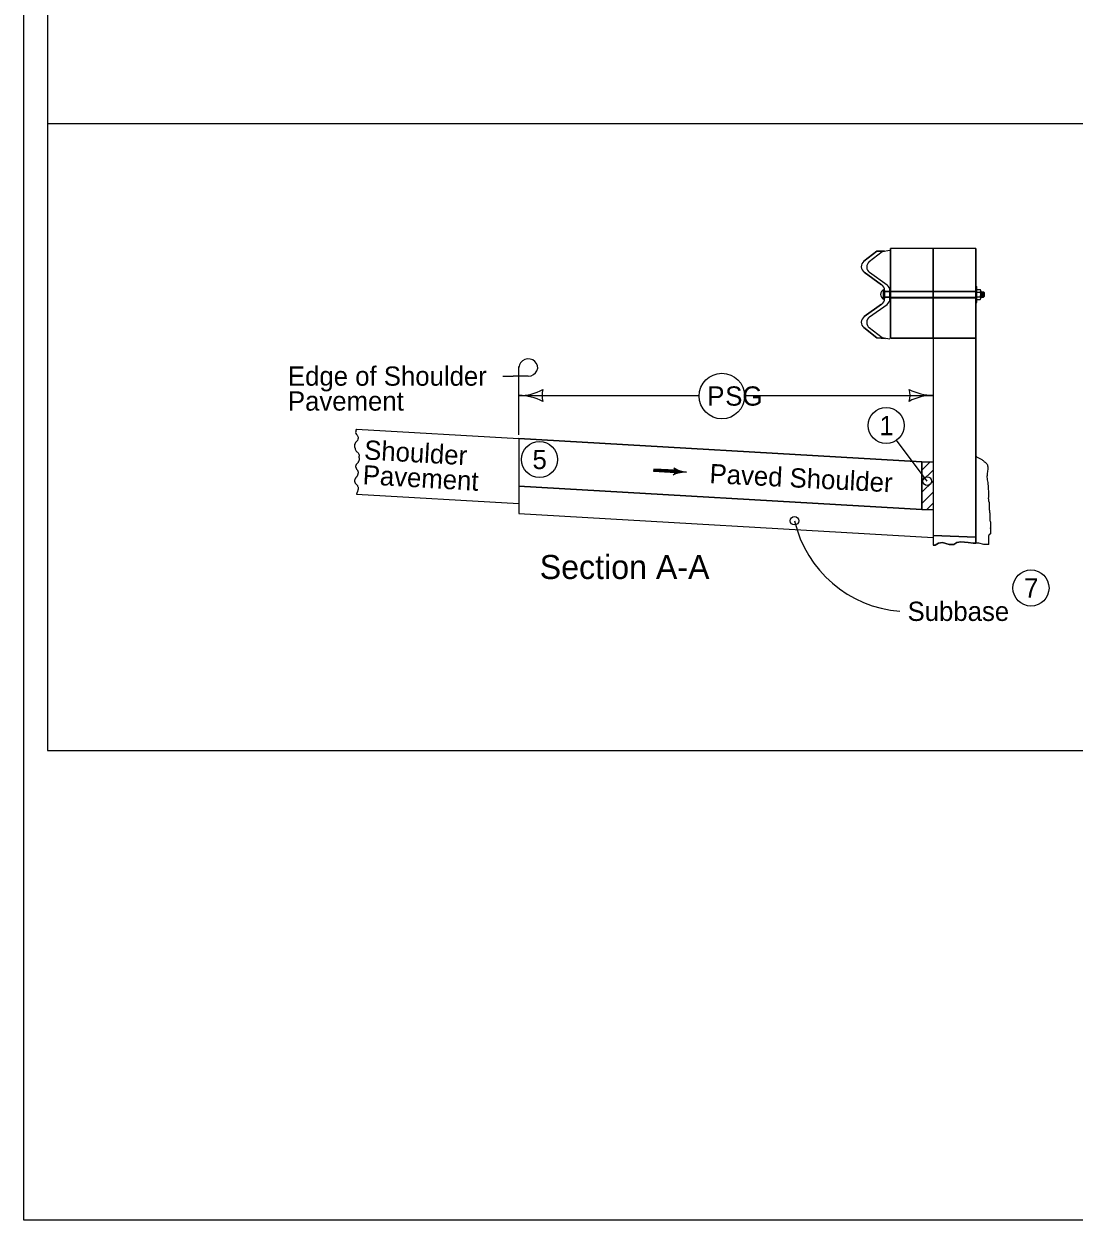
# Model space of a CAD drawing. Extents: x 10133 to 81668, y 5848 to 11018.
# Drawn here: x 10133 to 11006, y 7924 to 8918 of the extents above; entities that cross this region are included whole.
import ezdxf

# ---------------------------------------------------------------- set-up
doc = ezdxf.new("R2010")
doc.units = 0
for name, color, linetype in [('dsnStdLabel', 7, 'Continuous'), ('dsnStdLineWork', 7, 'Continuous'), ('dsnStdNote', 7, 'Continuous'), ('dsnStdShading', 7, 'Continuous'), ('Level 5', 7, 'Continuous'), ('PlanSheetShape', 7, 'Continuous'), ('SheetBorder', 7, 'Continuous'), ('SheetText', 7, 'Continuous'), ('ShtPlotShapeBatchPrint', 7, 'Continuous')]:
    doc.layers.add(name, color=color, linetype=linetype)

msp = doc.modelspace()

# ---------------------------------------------------------------- linework, layer by layer
at = {"layer": 'dsnStdLabel'}
for centre, radius in [((10849.44, 8584.52), 15), ((10561.16, 8556.33), 15), ((10883.56, 8538.4), 3.58), ((10969.88, 8449.47), 15)]:
    msp.add_circle(centre, radius, dxfattribs=at)
at = {"layer": 'dsnStdLineWork'}
for p, q in [((10924.05, 8731.84), (10852.96, 8731.84)), ((10852.96, 8657.19), (10852.96, 8731.84)), ((10888.5, 8657.19), (10888.5, 8731.84)), ((10924.05, 8731.84), (10924.05, 8486.8)), ((10831.02, 8721.08), (10841.78, 8729.48)), ((10835.45, 8720.85), (10846.22, 8729.26)), ((10841.78, 8729.48), (10848.11, 8729.59)), ((10846.22, 8729.26), (10852.56, 8730.38)), ((10845.72, 8701.54), (10831.21, 8711.96)), ((10850.19, 8701.31), (10835.63, 8711.76)), ((10847.34, 8689.44), (10847.34, 8697.52)), ((10847.34, 8695.83), (10852.77, 8695.83)), ((10847.34, 8691.17), (10852.96, 8691.17)), ((10848.12, 8690.1), (10848.11, 8696.91)), ((10848.11, 8690.1), (10848.12, 8693.51)), ((10848.12, 8693.51), (10848.12, 8690.1)), ((10848.29, 8695.83), (10852.96, 8695.83)), ((10852.56, 8693.29), (10852.56, 8696.69)), ((10852.56, 8689.88), (10852.56, 8693.29)), ((10852.56, 8693.29), (10852.56, 8689.88)), ((10852.96, 8696.17), (10924.05, 8696.17)), ((10852.96, 8695.83), (10924.05, 8695.83)), ((10852.96, 8691.17), (10924.05, 8691.17)), ((10924.05, 8700.14), (10924.73, 8700.14)), ((10924.73, 8686.8), (10924.73, 8700.14)), ((10924.73, 8697.51), (10927.7, 8697.51)), ((10924.73, 8695.49), (10927.7, 8695.49)), ((10924.73, 8691.45), (10927.7, 8691.45)), ((10928.06, 8690.44), (10928.06, 8696.5)), ((10928.06, 8695.8), (10930.43, 8695.8)), ((10928.06, 8691.14), (10930.43, 8691.14)), ((10928.95, 8695.8), (10928.95, 8691.14)), ((10929.69, 8695.8), (10929.69, 8691.14)), ((10930.43, 8695.8), (10930.88, 8695.27)), ((10930.43, 8695.8), (10930.43, 8691.14)), ((10930.88, 8691.67), (10930.43, 8691.14)), ((10930.88, 8695.27), (10930.88, 8691.67)), ((10831.21, 8675.05), (10845.72, 8685.47)), ((10835.63, 8674.82), (10850.19, 8685.27)), ((10852.95, 8690.83), (10924.05, 8690.83)), ((10924.05, 8686.8), (10924.73, 8686.8)), ((10924.73, 8689.43), (10927.7, 8689.43)), ((10841.78, 8657.54), (10831.02, 8665.93)), ((10846.22, 8657.32), (10835.45, 8665.73)), ((10848.88, 8656.85), (10841.78, 8657.54)), ((10852.56, 8656.2), (10846.22, 8657.32)), ((10888.5, 8657.19), (10852.96, 8657.19)), ((10888.5, 8657.19), (10888.5, 8484.96)), ((10408.97, 8581.57), (10544.11, 8573.71)), ((10544.11, 8573.71), (10544.11, 8519.7)), ((10544.11, 8573.71), (10879.25, 8554.23)), ((10879.25, 8547.48), (10885.99, 8554.23)), ((10879.25, 8547.48), (10885.99, 8554.23)), ((10879.25, 8547.48), (10885.99, 8554.23)), ((10879.25, 8547.48), (10885.99, 8554.23)), ((10879.25, 8554.23), (10888.49, 8554.23)), ((10879.25, 8554.23), (10879.25, 8514.8)), ((10879.25, 8538.3), (10888.49, 8547.53)), ((10879.25, 8538.3), (10888.49, 8547.53)), ((10879.25, 8538.3), (10888.49, 8547.53)), ((10879.25, 8538.3), (10888.49, 8547.53)), ((10934.1, 8547.46), (10934.1, 8547.46)), ((10879.25, 8514.8), (10544.11, 8534.12)), ((10879.25, 8529.07), (10888.49, 8538.31)), ((10879.25, 8529.07), (10888.49, 8538.31)), ((10879.25, 8529.07), (10888.49, 8538.31)), ((10879.25, 8529.07), (10888.49, 8538.31)), ((10409, 8527.56), (10544.11, 8519.7)), ((10879.25, 8519.84), (10888.49, 8529.08)), ((10544.11, 8519.7), (10544.11, 8511.28)), ((10879.25, 8514.8), (10888.49, 8514.8)), ((10883.35, 8514.8), (10888.49, 8519.94)), ((10544.11, 8511.28), (10888.5, 8491.42))]:
    msp.add_line(p, q, dxfattribs=at)
for points in [[(10928.05, 8690.76), (10928, 8691.03), (10927.96, 8691.2), (10927.87, 8691.36), (10927.75, 8691.45), (10927.83, 8691.55), (10927.91, 8691.77), (10927.97, 8692.08), (10928.05, 8692.83), (10928.05, 8690.76), (10928.03, 8690.9), (10927.99, 8691.12), (10927.91, 8691.33), (10927.79, 8691.44), (10927.83, 8691.53), (10927.89, 8691.68), (10927.99, 8692.18), (10928.03, 8692.56), (10928.03, 8690.95), (10928, 8691.07), (10927.96, 8691.24), (10927.83, 8691.44), (10927.88, 8691.61), (10927.96, 8691.94), (10928.02, 8692.27), (10928.01, 8691.11), (10927.97, 8691.24), (10927.86, 8691.43), (10927.9, 8691.65), (10927.96, 8691.9), (10927.99, 8692.08), (10927.99, 8691.21), (10927.93, 8691.32), (10927.88, 8691.43), (10927.97, 8691.89), (10927.97, 8691.29), (10927.9, 8691.43), (10927.95, 8691.72), (10927.95, 8691.37), (10927.92, 8691.44), (10927.93, 8691.54), (10927.93, 8691.46)], [(10927.76, 8695.49), (10927.83, 8695.54), (10927.91, 8695.64), (10927.99, 8695.86), (10928.05, 8696.15), (10928.05, 8694.2), (10927.99, 8694.71), (10927.94, 8695.08), (10927.82, 8695.41), (10927.76, 8695.49), (10927.82, 8695.5), (10927.92, 8695.65), (10928.01, 8695.87), (10928.03, 8696.03), (10928.03, 8694.49), (10927.96, 8694.98), (10927.9, 8695.25), (10927.8, 8695.47), (10927.83, 8695.48), (10927.97, 8695.7), (10928.01, 8695.85), (10928.01, 8694.75), (10927.82, 8695.46), (10927.99, 8695.74), (10927.99, 8694.88), (10927.85, 8695.45), (10927.97, 8695.67), (10927.98, 8695.03), (10927.87, 8695.43), (10927.96, 8695.6), (10927.96, 8695.19), (10927.89, 8695.42), (10927.94, 8695.53), (10927.94, 8695.33), (10927.91, 8695.4), (10927.92, 8695.45)], [(10934.57, 8523.62), (10934.51, 8523.35), (10934.51, 8523.15), (10934.51, 8522.95), (10934.51, 8522.76), (10934.51, 8522.56), (10934.51, 8522.37), (10934.51, 8522.08), (10934.51, 8521.88), (10934.61, 8521.59), (10934.71, 8521.29), (10934.9, 8521.1), (10934.9, 8520.9), (10935, 8520.71), (10935, 8520.51), (10935, 8520.32), (10935.1, 8520.22), (10935.1, 8520.02), (10935.1, 8519.83), (10935.1, 8519.63), (10935.1, 8519.44), (10935.1, 8519.24), (10935.1, 8518.95), (10935.1, 8518.66), (10935.1, 8518.46), (10935.1, 8518.17), (10935.1, 8517.97), (10935.1, 8517.78), (10935.2, 8517.68), (10935.2, 8517.48), (10935.2, 8517.29), (10935.2, 8517.09), (10935.2, 8516.9), (10935.2, 8516.7), (10935.2, 8516.51), (10935.2, 8516.31), (10935.2, 8516.12), (10935.2, 8515.92), (10935.2, 8515.72), (10935.2, 8515.53), (10935.2, 8515.33), (10935.2, 8515.14), (10935.2, 8514.94), (10935.2, 8514.75), (10935.2, 8514.55), (10935.2, 8514.36), (10935.2, 8514.16), (10935.29, 8514.06), (10935.29, 8513.87), (10935.29, 8513.67), (10935.39, 8513.57), (10935.39, 8513.38), (10935.39, 8513.18), (10935.49, 8513.09), (10935.49, 8512.89), (10935.49, 8512.7), (10935.49, 8512.5), (10935.49, 8512.21), (10935.59, 8511.91), (10935.59, 8511.72), (10935.59, 8511.52), (10935.59, 8511.33), (10935.59, 8511.13), (10935.59, 8510.94), (10935.59, 8510.74), (10935.59, 8510.55), (10935.59, 8510.35), (10935.59, 8510.16), (10935.59, 8509.96), (10935.59, 8509.76), (10935.59, 8509.57), (10935.59, 8509.37), (10935.59, 8509.18), (10935.59, 8508.98), (10935.59, 8508.79), (10935.59, 8508.59), (10935.59, 8508.4), (10935.59, 8508.2), (10935.59, 8508.01), (10935.59, 8507.81), (10935.59, 8507.61), (10935.59, 8507.42), (10935.59, 8507.22), (10935.59, 8507.03), (10935.59, 8506.83), (10935.59, 8506.64), (10935.59, 8506.44), (10935.59, 8506.25), (10935.68, 8506.15), (10935.68, 8505.86), (10935.68, 8505.66), (10935.78, 8505.47), (10935.88, 8505.17), (10935.88, 8504.98), (10935.98, 8504.88), (10935.98, 8504.68), (10936.07, 8504.59), (10936.17, 8504.49), (10936.17, 8504.29), (10936.17, 8504.1), (10936.17, 8503.9), (10936.27, 8503.8), (10936.27, 8503.61), (10936.27, 8503.41), (10936.27, 8503.22), (10936.27, 8503.02), (10936.27, 8502.83), (10936.27, 8502.63), (10936.27, 8502.44), (10936.27, 8502.24), (10936.27, 8502.05), (10936.27, 8501.85), (10936.27, 8501.65), (10936.27, 8501.46), (10936.27, 8501.26), (10936.27, 8501.07), (10936.27, 8500.87), (10936.27, 8500.68), (10936.27, 8500.48), (10936.27, 8500.29), (10936.27, 8500.09), (10936.27, 8499.9), (10936.27, 8499.7), (10936.27, 8499.51), (10936.27, 8499.31), (10936.27, 8499.11), (10936.27, 8498.92), (10936.27, 8498.92), (10936.27, 8499.21), (10936.27, 8499.41), (10936.27, 8499.6), (10936.27, 8499.41), (10936.27, 8499.21), (10936.27, 8499.02), (10936.27, 8498.82), (10936.27, 8498.63), (10936.27, 8498.43), (10936.27, 8498.24), (10936.27, 8498.04), (10936.27, 8497.84), (10936.27, 8497.65), (10936.27, 8497.45), (10936.27, 8497.26), (10936.27, 8497.06), (10936.27, 8496.87), (10936.27, 8496.67), (10936.17, 8496.57), (10936.17, 8496.38), (10936.17, 8496.18), (10936.17, 8495.99), (10936.17, 8495.79), (10936.17, 8495.6), (10936.17, 8495.4), (10936.17, 8495.21), (10936.17, 8495.01), (10936.17, 8494.82), (10936.17, 8494.62), (10936.07, 8494.52), (10935.98, 8494.33), (10935.88, 8494.23), (10935.78, 8494.13), (10935.68, 8494.03), (10935.49, 8493.94), (10935.29, 8493.94), (10935.2, 8493.84), (10935.1, 8493.74), (10935, 8493.64), (10934.8, 8493.55), (10934.71, 8493.45), (10934.71, 8493.25), (10934.61, 8493.15), (10934.61, 8492.96), (10934.61, 8492.76), (10934.61, 8492.57), (10934.61, 8485.75)], [(10934.74, 8485.75), (10930.59, 8485.63), (10926.46, 8486.8), (10921.9, 8486.8), (10917.66, 8487.22), (10911.41, 8487.96), (10908.33, 8487.33), (10905.68, 8485.53), (10901.97, 8485.74), (10896.36, 8487.33), (10893.07, 8486.8), (10890.31, 8485.21), (10888.5, 8484.96)]]:
    msp.add_lwpolyline(points, dxfattribs=at)
for centre, radius, start, end in [((10834.49, 8716.59), 5.68, 127.75002, 234.69086), ((10838.94, 8716.37), 5.68, 127.75002, 234.69086), ((10842.44, 8696.91), 5.68, 360, 54.69099), ((10846.88, 8696.69), 5.68, 360, 54.69099), ((10849.42, 8693.49), 4.54, 117.20289, 242.8461), ((10842.44, 8690.1), 5.68, 305.30901, 0), ((10846.88, 8689.88), 5.68, 305.30901, 0), ((10834.49, 8670.42), 5.68, 125.30914, 232.24998), ((10838.94, 8670.2), 5.68, 125.30914, 232.24998)]:
    msp.add_arc(centre, radius, start, end, dxfattribs=at)
for centre in [(10927.7, 8696.5), (10927.7, 8690.44)]:
    msp.add_ellipse(centre, major_axis=(0, -1.01), ratio=0.362258, start_param=6.283156, end_param=9.424748, dxfattribs=at)
for points in [[(10408.97, 8581.57), (10408.47, 8577.97), (10409.51, 8576.47), (10410.38, 8574.17), (10409.77, 8572.11), (10407.86, 8569.73), (10407.34, 8567.83), (10407.86, 8565.54), (10408.73, 8563.16), (10409.77, 8562.45), (10411.16, 8559.91), (10411.15, 8559.07)], [(10409.18, 8541.96), (10409.39, 8542.21), (10409.59, 8542.47), (10409.94, 8543.03), (10410.23, 8543.62), (10410.34, 8543.93), (10410.44, 8544.24), (10410.57, 8544.86), (10410.62, 8545.48), (10410.58, 8546.07), (10410.52, 8546.35), (10410.48, 8546.48), (10410.43, 8546.61), (10410.23, 8546.99), (10409.94, 8547.35), (10409.64, 8547.72), (10409.39, 8548.12), (10409.25, 8548.4), (10409.12, 8548.68), (10408.86, 8549.26), (10408.65, 8549.82), (10408.58, 8550.12), (10408.53, 8550.41), (10408.52, 8550.54), (10408.52, 8550.67), (10408.67, 8551.44), (10408.88, 8551.96), (10409.13, 8552.47), (10409.58, 8553.11), (10410.1, 8553.65), (10410.61, 8554.2), (10410.84, 8554.51), (10411.04, 8554.85), (10411.25, 8555.32), (10411.4, 8555.8), (10411.51, 8556.27), (10411.54, 8556.51), (10411.55, 8556.63), (10411.56, 8556.75), (10411.51, 8557.26), (10411.36, 8557.77), (10411.31, 8557.9), (10411.26, 8558.03), (10411.21, 8558.15), (10411.18, 8558.29), (10411.15, 8559.07)], [(10934.57, 8523.62), (10934.89, 8526.52), (10934.67, 8531.39), (10934.23, 8537.14), (10933.56, 8541.56), (10933.78, 8544.88), (10934.23, 8549.08), (10933.56, 8552.17), (10931.35, 8554.16), (10929.36, 8555.93), (10927.15, 8557.04), (10924.94, 8558.36), (10924.06, 8559.03)], [(10409.18, 8541.96), (10408.97, 8541.73), (10408.72, 8541.49), (10408.49, 8541.25), (10408.3, 8540.98), (10408.16, 8540.7), (10408.02, 8540.41), (10407.76, 8539.84), (10407.65, 8539.56), (10407.56, 8539.27), (10407.49, 8538.98), (10407.46, 8538.83), (10407.44, 8538.68), (10407.45, 8538.17), (10407.58, 8537.65), (10407.79, 8537.14), (10408.04, 8536.63), (10408.49, 8535.99), (10409.01, 8535.44), (10409.52, 8534.9), (10409.75, 8534.59), (10409.95, 8534.25), (10410.35, 8533.3), (10410.46, 8532.83), (10410.47, 8532.35), (10410.43, 8532.06), (10410.39, 8531.77), (10410.33, 8531.49), (10410.26, 8531.2), (10409.95, 8530.05), (10409.77, 8529.44), (10409.58, 8528.84), (10409.35, 8528.25), (10409.22, 8527.96), (10409.08, 8527.68), (10409, 8527.56)]]:
    msp.add_spline(points, degree=3, dxfattribs=at)
at = {"layer": 'dsnStdNote'}
msp.add_circle((10773.25, 8505.44), 3.54, dxfattribs=at)
msp.add_circle((10773.25, 8505.44), 3.54, dxfattribs=at)
at = {"layer": 'dsnStdShading'}
for p, q in [((12307.76, 8835.36), (10152.18, 8835.36)), ((10883.56, 8538.4), (10858.18, 8572.33))]:
    msp.add_line(p, q, dxfattribs=at)
at = {"layer": 'Level 5'}
msp.add_circle((10561.16, 8556.33), 15, dxfattribs=at)
at = {"layer": 'PlanSheetShape'}
for p, q in [((10831.21, 8711.96), (10845.72, 8701.54)), ((10845.72, 8685.47), (10831.21, 8675.05)), ((10879.25, 8554.23), (10544.11, 8573.71)), ((10544.11, 8573.71), (10544.11, 8534.12)), ((10879.25, 8514.8), (10879.25, 8554.23)), ((10544.11, 8534.12), (10879.25, 8514.8))]:
    msp.add_line(p, q, dxfattribs=at)
for points in [[(10888.5, 8696.17), (10888.5, 8731.84), (10852.96, 8731.84), (10852.96, 8696.17), (10852.96, 8696.17), (10888.5, 8696.17)], [(10924.05, 8696.17), (10924.05, 8700.16), (10924.05, 8731.84), (10888.5, 8731.84), (10888.5, 8696.17), (10924.05, 8696.17)], [(10835.46, 8720.86), (10835.45, 8720.85), (10846.22, 8729.26), (10848.11, 8729.59), (10841.78, 8729.48), (10831.02, 8721.08)], [(10850.16, 8701.33), (10850.19, 8701.31), (10835.63, 8711.76), (10835.66, 8711.74)], [(10848.11, 8696.91), (10848.11, 8695.83), (10852.56, 8695.83), (10852.56, 8696.69), (10852.56, 8696.69)], [(10852.56, 8689.88), (10852.56, 8689.88), (10852.56, 8691.17), (10848.12, 8691.17), (10848.12, 8690.1), (10848.12, 8691.17), (10848.11, 8691.17), (10848.11, 8690.1)], [(10852.96, 8695.83), (10852.96, 8691.17), (10852.96, 8691.17), (10888.5, 8691.17), (10888.5, 8695.83), (10852.96, 8695.83), (10852.96, 8695.83)], [(10924.05, 8691.17), (10924.05, 8695.83), (10888.5, 8695.83), (10888.5, 8691.17), (10924.05, 8691.17)], [(10835.66, 8674.84), (10835.63, 8674.82), (10850.19, 8685.27), (10850.16, 8685.25)], [(10852.96, 8690.83), (10852.96, 8657.19), (10888.5, 8657.19), (10888.5, 8690.83), (10852.96, 8690.83)], [(10924.05, 8657.19), (10924.05, 8686.83), (10924.05, 8690.83), (10888.5, 8690.83), (10888.5, 8657.19), (10924.05, 8657.19)], [(10831.02, 8665.93), (10841.78, 8657.54), (10848.88, 8656.85), (10846.22, 8657.32), (10835.45, 8665.73), (10835.46, 8665.71)], [(10924.05, 8491.85), (10924.05, 8657.19), (10888.5, 8657.19), (10888.5, 8554.22), (10888.5, 8547.53), (10888.5, 8547.53), (10888.5, 8547.53), (10888.5, 8538.3), (10888.5, 8538.3), (10888.5, 8538.3), (10888.5, 8529.16), (10888.5, 8529.16), (10888.5, 8529.16), (10888.5, 8522.23), (10888.5, 8493.01), (10924.05, 8491.85)], [(10924.05, 8491.85), (10888.5, 8493.01), (10888.5, 8484.96), (10890.31, 8485.21), (10893.07, 8486.8), (10896.36, 8487.33), (10901.97, 8485.74), (10905.68, 8485.53), (10908.33, 8487.33), (10911.41, 8487.96), (10917.66, 8487.22), (10921.9, 8486.8), (10924.05, 8486.8), (10924.05, 8491.85)]]:
    msp.add_lwpolyline(points, dxfattribs=at)
msp.add_lwpolyline([(10852.56, 8695.83), (10848.11, 8695.83), (10848.11, 8692.37), (10848.12, 8693.51), (10848.12, 8691.17), (10852.56, 8691.17)], close=True, dxfattribs=at)
for centre, start, end in [((10834.49, 8716.59), 127.75002, 234.69086), ((10838.94, 8716.37), 127.75002, 234.69086), ((10842.44, 8696.91), 0, 54.69099), ((10846.88, 8696.69), 0, 54.69099), ((10842.44, 8690.1), 305.30901, 0), ((10846.88, 8689.88), 305.30901, 0), ((10834.49, 8670.42), 125.30914, 232.24998), ((10838.94, 8670.2), 125.30914, 232.24998)]:
    msp.add_arc(centre, 5.68, start, end, dxfattribs=at)
at = {"layer": 'SheetBorder'}
msp.add_lwpolyline([(10132.52, 9944.02), (13267.53, 9944.02), (13267.53, 7924.02), (10132.52, 7924.02)], close=True, dxfattribs=at)
at = {"layer": 'SheetText'}
for p, q in [((10544.11, 8612.79), (10544.11, 8633.65)), ((10530.74, 8625.64), (10539.43, 8625.64)), ((10551.92, 8625.64), (10539.43, 8625.64)), ((10544.11, 8576.86), (10544.11, 8612.79)), ((10544.11, 8609.47), (10693.94, 8609.47)), ((10731.8, 8609.63), (10888.5, 8609.63)), ((10674.32, 8546.37), (10656.11, 8547.42)), ((10674.21, 8545.43), (10674.21, 8545.43)), ((10674.33, 8547.37), (10674.33, 8547.37))]:
    msp.add_line(p, q, dxfattribs=at)
for points in [[(10674.34, 8547.31), (10656.18, 8548.36), (10656.05, 8546.48), (10674.21, 8545.43), (10674.27, 8547.04), (10656.4, 8548.14), (10656.34, 8546.64), (10673.83, 8545.69), (10673.95, 8546.81), (10656.63, 8547.87), (10656.61, 8546.87), (10673.62, 8545.89), (10673.71, 8546.59), (10656.82, 8547.65), (10656.8, 8547.09), (10673.41, 8546.15)], [(10673.94, 8548.56), (10674.63, 8547.4), (10674.61, 8545.75), (10673.85, 8544.35), (10676.61, 8545.22), (10679.8, 8545.87), (10680.7, 8546), (10678.46, 8546.55), (10675.23, 8547.78), (10674.29, 8548.31), (10674.41, 8544.8), (10679.36, 8546.02), (10674.72, 8547.6), (10674.73, 8545.18), (10678.13, 8546.11), (10675.13, 8546.97), (10674.9, 8545.59), (10677.06, 8546.09), (10675.47, 8546.6), (10675.33, 8545.94), (10676.12, 8546.1)]]:
    msp.add_lwpolyline(points, dxfattribs=at)
msp.add_circle((10712.87, 8609.07), 18.93, dxfattribs=at)
for centre, radius, start, end in [((10544.11, 8651.97), 42.5, 270, 298.07249), ((10579.75, 8609.47), 16.42, 162.26665, 197.73335), ((10852.87, 8609.63), 16.42, 342.26665, 17.73335), ((10888.5, 8652.13), 42.5, 241.92751, 270), ((10544.11, 8566.97), 42.5, 61.92751, 90), ((10888.5, 8567.13), 42.5, 90, 118.07249), ((10868.48, 8527.56), 97.76, 193.07698, 265.55799)]:
    msp.add_arc(centre, radius, start, end, dxfattribs=at)
for centre, major_axis, start_param, end_param in [((10551.92, 8632.78), (-7.81, 0), 1.570796, 6.283185), ((10670.55, 8546.58), (3.88, 0), 5.202895, 7.237436), ((10682.82, 8525.59), (22.17, 0), 1.537172, 2.061295), ((10685.61, 8566.01), (-22.17, 0), 0.954258, 1.478381)]:
    msp.add_ellipse(centre, major_axis=major_axis, ratio=0.913811, start_param=start_param, end_param=end_param, dxfattribs=at)
at = {"layer": 'ShtPlotShapeBatchPrint'}
for p, q in [((10152.18, 9924.36), (10152.18, 8314.36)), ((10152.18, 8314.36), (13247.87, 8314.36))]:
    msp.add_line(p, q, dxfattribs=at)

# ---------------------------------------------------------------- texts
at = {"layer": 'dsnStdLabel'}
for s, p in [('1', (10843.82, 8576.52)), ('5', (10555.39, 8548.33)), ('7', (10964.18, 8441.47))]:
    msp.add_text(s, height=16, dxfattribs=at).set_placement(p)
at = {"layer": 'SheetText'}
for s, height, p in [('Edge of Shoulder ', 16, (10352.05, 8617.64)), ('Pavement', 16, (10352.05, 8596.93)), ('P', 16, (10700.74, 8601.07)), ('SG', 16, (10715.66, 8601.07)), ('Section A-A', 20, (10561.37, 8456.94)), ('Subbase', 16, (10867.26, 8422.09))]:
    msp.add_text(s, height=height, dxfattribs=at).set_placement(p)
for s, rotation, p in [('Shoulder', 356.73462, (10415.1, 8556.4)), ('Paved Shoulder ', 357.0678, (10702.33, 8536.73)), ('Pavement', 356.73462, (10413.92, 8535.73))]:
    msp.add_text(s, height=16, rotation=rotation, dxfattribs=at).set_placement(p)

doc.saveas('drawing.dxf')
